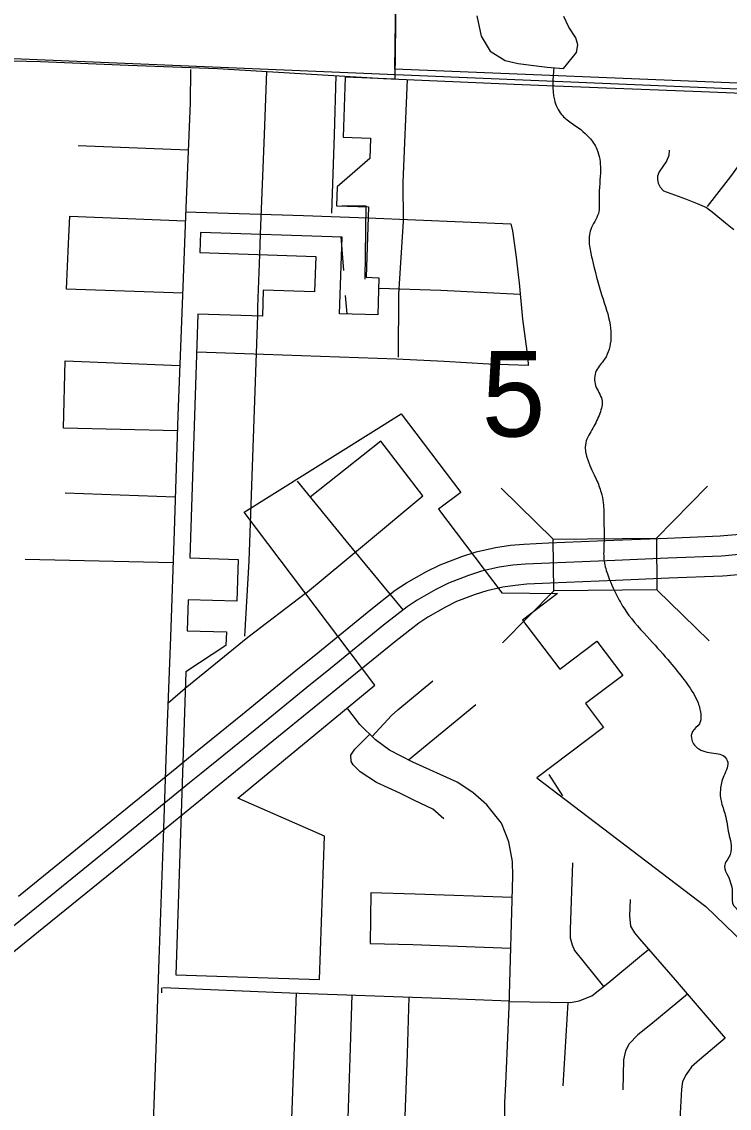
# Model space of a CAD drawing. Extents: x 1219626 to 1426462, y 456797 to 752399.
# Drawn here: x 1346385 to 1349894, y 558376 to 563770 of the extents above; entities that cross this region are included whole.
import ezdxf

# ---------------------------------------------------------------- set-up
doc = ezdxf.new("R2010")
doc.units = 0
for name, color, linetype in [('Bridges', 7, 'Continuous'), ('Cities Incorporated Area', 7, 'Continuous'), ('City Streets', 7, 'Continuous'), ('Connecting Roads', 7, 'Continuous'), ('County Routes Highway Center Lines', 7, 'Continuous'), ('Lakes and Ponds', 7, 'Continuous'), ('Local Roads Paved', 7, 'Continuous'), ('Masks', 7, 'Continuous'), ('Narrow River Creek and Branch and Slough', 7, 'Continuous'), ('Section Lines', 7, 'Continuous'), ('Section Numbers', 7, 'Continuous'), ('State Route Divided Highway Outline and Fill', 7, 'Continuous'), ('State Routes Highway Center Lines', 7, 'Continuous')]:
    doc.layers.add(name, color=color, linetype=linetype)

msp = doc.modelspace()

# ---------------------------------------------------------------- linework, layer by layer
at = {"layer": 'Bridges'}
for p, q in [((1349021, 561201.4), (1348762.5, 561454.9)), ((1349533, 561206.4), (1349786.5, 561464.9)), ((1349023.5, 560945.4), (1348770, 560687)), ((1349535.5, 560950.4), (1349794, 560696.9))]:
    msp.add_line(p, q, dxfattribs=at)
msp.add_lwpolyline([(1349021, 561201.4), (1349533, 561206.4), (1349535.5, 560950.4), (1349023.5, 560945.4)], close=True, dxfattribs=at)
at = {"layer": 'Cities Incorporated Area'}
for p, q in [((1348335.1, 571362.3), (1348234.8, 563484.7)), ((1347988.5, 563494), (1347978.7, 563196.1)), ((1348234.8, 563484.7), (1347988.5, 563494)), ((1347978.7, 563196.1), (1348114.4, 563191.6)), ((1348114.4, 563191.6), (1348111.1, 563091)), ((1348111.1, 563091), (1347949.3, 562950.4)), ((1347949.3, 562950.4), (1347946.2, 562855.8)), ((1347946.2, 562855.8), (1348104.7, 562850.6)), ((1348104.7, 562850.6), (1348093.2, 562501.2)), ((1347271, 562724.3), (1347267.7, 562623.9)), ((1347973.7, 562701.2), (1347271, 562724.3)), ((1347961.2, 562320.6), (1347973.7, 562701.2)), ((1347267.7, 562623.9), (1347843, 562605)), ((1347843, 562605), (1347837.2, 562428.5)), ((1348093.2, 562501.2), (1348156.7, 562499.1)), ((1348156.7, 562499.1), (1348150.6, 562314.4)), ((1347582.8, 562436.8), (1347578.6, 562308.4)), ((1347837.2, 562428.5), (1347582.8, 562436.8)), ((1347257.7, 562319), (1347217.8, 561108.5)), ((1347578.6, 562308.4), (1347257.7, 562319)), ((1348150.6, 562314.4), (1347961.2, 562320.6)), ((1347487.7, 561334.6), (1348267, 561823.6)), ((1348267, 561823.6), (1348562.1, 561433)), ((1348562.1, 561433), (1348452.4, 561350.2)), ((1348136.2, 560476.3), (1347487.7, 561334.6)), ((1348452.4, 561350.2), (1348765.8, 560935.4)), ((1347217.8, 561108.5), (1347457.8, 561100.6)), ((1347457.8, 561100.6), (1347451, 560893.1)), ((1348765.8, 560935.4), (1349042.6, 560931.8)), ((1347211, 560901), (1347206, 560747.1)), ((1347451, 560893.1), (1347211, 560901)), ((1349042.6, 560931.8), (1348868.2, 560800)), ((1348868.2, 560800), (1349053, 560555.4)), ((1347206, 560747.1), (1347400.1, 560740.7)), ((1347400.1, 560740.7), (1347397.8, 560673.1)), ((1347397.8, 560673.1), (1347199.2, 560542.9)), ((1349053, 560555.4), (1349237.4, 560694.7)), ((1349237.4, 560694.7), (1349365.6, 560525)), ((1347199.2, 560542.9), (1347149.7, 559038.5)), ((1349365.6, 560525), (1349181.2, 560385.7)), ((1347456.6, 559916), (1348136.2, 560476.3)), ((1349181.2, 560385.7), (1349271, 560266.8)), ((1349271, 560266.8), (1348938.9, 560015.9)), ((1347885.7, 559727.7), (1347456.6, 559916)), ((1347862.3, 559015), (1347885.7, 559727.7)), ((1347149.7, 559038.5), (1347862.3, 559015))]:
    msp.add_line(p, q, dxfattribs=at)
msp.add_lwpolyline([(1348938.9, 560015.9), (1349778.8, 559377.2), (1349968.8, 559194.8), (1350791.9, 558387.4)], dxfattribs=at)
at = {"layer": 'City Streets'}
for p, q in [((1346664.8, 563155), (1347210.1, 563134)), ((1347568.2, 562715.3), (1347564.8, 562612.2)), ((1346600.9, 561431), (1347146.3, 561411.6)), ((1346401.5, 561102.8), (1347135.4, 561085.4)), ((1347196, 560460.1), (1347109.7, 560385.5)), ((1348302.9, 560105.5), (1348636.9, 560381)), ((1349071.1, 558487.3), (1349095.6, 558901.7))]:
    msp.add_line(p, q, dxfattribs=at)
for points in [[(1347598.8, 563523.1), (1347587, 563209.6), (1347568.2, 562715.3)], [(1347942.7, 563502.4), (1347934.7, 563208.7), (1347921.9, 562819.3)], [(1347196.9, 562826.7), (1347782.1, 562807.3), (1348100.9, 562796.2)], [(1347183, 562422.4), (1346606, 562442.6), (1346617.1, 562666.7), (1346623.1, 562804.8), (1347195.3, 562781.3)], [(1347564.8, 562612.2), (1347554.6, 562354.8), (1347553.7, 562311.3)], [(1347157.4, 561738.9), (1346592.4, 561753.1), (1346600.9, 562086.3), (1347169.4, 562063.2)], [(1347791.9, 560932.4), (1348084.2, 561175.3), (1348374.9, 561416.5), (1348166.1, 561688.3), (1347815.1, 561410.4)], [(1347751, 561488.9), (1347993.1, 561192.3), (1348275.5, 560850)], [(1348122.5, 560221.9), (1348219.3, 560326.4), (1348250, 560354.6), (1348423.9, 560497.8)], [(1348750.7, 556857.9), (1348759.6, 557059), (1348770.7, 557242.2), (1348775.8, 557428), (1348795.4, 557951.3), (1348798, 558065.5), (1348792, 558147.3), (1348788.6, 558198.4), (1348781, 558286.2), (1348781, 558404.6), (1348786.1, 558497.5), (1348803.1, 558880.2), (1348820.2, 559528.8), (1348818.5, 559602), (1348800.6, 559699.2), (1348763.9, 559792.1), (1348691.5, 559883.3), (1348622.4, 559943.8), (1348544.9, 559994.9), (1348324.2, 560094.6), (1348209.1, 560153.4), (1348140.1, 560204.6), (1348061.7, 560282.1), (1348002.9, 560358.8)], [(1348478.3, 559812.5), (1348423.9, 559861.1), (1348330.1, 559905.4), (1348259.4, 559940.4), (1348144.3, 559994.1), (1348064.2, 560046.9), (1348029.3, 560081.9), (1348018.2, 560098), (1348017.3, 560129.6), (1348036.9, 560159.4), (1348111.5, 560232.9)], [(1349115.9, 559595.2), (1349105.7, 559263.7), (1349105.7, 559222.8), (1349114.2, 559187.9), (1349127, 559158.9), (1349269.9, 558980.5)], [(1348817.4, 559422.2), (1348336.1, 559439.3), (1348117.1, 559445.2), (1348113.6, 559193.8), (1348325, 559188.7), (1348810.8, 559171.1)], [(1349402.2, 559412.8), (1349398.8, 559331), (1349404.8, 559279.9), (1349424.4, 559247.5), (1349448.3, 559216.8), (1349626.4, 559013.1), (1349873.5, 558724.2), (1349746.5, 558616.9), (1349706.5, 558581.9), (1349680.1, 558544.4), (1349663, 558508.6), (1349657.9, 558471.1), (1349641.5, 558173.6)], [(1348803.8, 558906.9), (1349107.4, 558901.5), (1349150, 558909.2), (1349213, 558934.7), (1349291.4, 558997.8), (1349459.3, 559136.7), (1349493.7, 559164.8)], [(1347085.4, 558975.6), (1347715.2, 558950.1), (1348464.3, 558922.8), (1348803.9, 558910)], [(1347745.4, 558949), (1347734.8, 558636.5), (1347719.5, 558235)], [(1347999.9, 558228.2), (1348014.4, 558624.5), (1348024.3, 558938.8)], [(1349686.3, 558943), (1349505.4, 558792.8), (1349441, 558740.4), (1349398.4, 558697), (1349379.7, 558661.2), (1349370.3, 558616), (1349366, 558467.7)], [(1348304.5, 558928.6), (1348296.5, 558645.8), (1348280.3, 558204.4), (1348474.6, 558200.1)]]:
    msp.add_lwpolyline(points, dxfattribs=at)
at = {"layer": 'Connecting Roads'}
msp.add_lwpolyline([(1347222.4, 563532.6), (1347219.4, 563368.1), (1347198.1, 562845.7), (1347179.4, 562324.1), (1347158.9, 561815.3), (1347141, 561240.9), (1347122.3, 560715.1), (1347103.5, 560205.4), (1347085.6, 559717.1), (1347065.2, 559114.6), (1347048.1, 558622.8), (1347029.4, 558124.3)], dxfattribs=at)
at = {"layer": 'County Routes Highway Center Lines'}
msp.add_lwpolyline([(1341197, 563735.1), (1341867.5, 563703.6), (1342500.1, 563681.3), (1343520.8, 563640.5), (1344311.5, 563612.4), (1345034.4, 563604.6), (1345994.9, 563583.3), (1346478.1, 563572.6), (1346912.8, 563555.1), (1347356.2, 563537.7), (1348178.9, 563488.2), (1348828, 563460.1), (1349028.9, 563452.3), (1349756.5, 563423.2), (1350691.9, 563386.3), (1351274, 563363), (1351525.3, 563348.5), (1351971.6, 563324.2)], dxfattribs=at)
msp.add_arc((1345880.6, 559007), 1200, 357.2434, 358.4008, dxfattribs=at)
at = {"layer": 'Lakes and Ponds'}
for points in [[(1348642.1, 563798.7), (1348663.4, 563699), (1348708.2, 563624.2), (1348782.4, 563578.1), (1348846.5, 563563), (1348911.2, 563554.3), (1348991.5, 563545.2), (1349071.8, 563538.4)], [(1349071.8, 563538.4), (1349135.9, 563616.6), (1349143.2, 563655.4), (1349132.7, 563690.5), (1349097.8, 563742.7), (1349073.8, 563796.1)]]:
    msp.add_lwpolyline(points, dxfattribs=at)
at = {"layer": 'Local Roads Paved'}
for points in [[(1348253.5, 562104.4), (1348256, 562417.4), (1348279, 562779.8), (1348277.3, 562972.9), (1348297.6, 563483)], [(1349934.3, 563159.2), (1349943.7, 563119.2), (1349942.8, 563078.4), (1349935.2, 563050.3), (1349900.3, 563000.9), (1349784.6, 562852.1)], [(1349596.8, 563132.8), (1349594.1, 563106.4), (1349582.2, 563078.4), (1349565.2, 563051.1), (1349546.5, 563024.8), (1349538.8, 563002.6), (1349537.9, 562986.5), (1349541.3, 562967.8), (1349550.7, 562948.2), (1349568.6, 562931.2), (1349676.6, 562891.2), (1349734.4, 562867.4), (1349781.2, 562847), (1349817, 562819.8), (1349875.6, 562771.3), (1349917.3, 562738.1)], [(1348100.9, 562796.2), (1348811.5, 562767), (1348819.2, 562731.3), (1348837, 562602), (1348847.2, 562513.5), (1348851.5, 562473.5), (1348869.3, 562293.2), (1348894.9, 562098.4), (1348896.6, 562063.5), (1348700.9, 562069.5), (1348480.6, 562084), (1348243.3, 562094.2), (1347583.2, 562118.8), (1347254.8, 562129)], [(1348157.4, 562447.2), (1348463.6, 562437), (1348857, 562418.2)], [(1347553.7, 562311.3), (1347511.1, 561091.8), (1347489, 560720.2)], [(1347791.9, 560932.4), (1347506.9, 560712.5), (1347196, 560460.1)]]:
    msp.add_lwpolyline(points, dxfattribs=at)
at = {"layer": 'Masks'}
for p, q in [((1348093.2, 562854.4), (1347971.8, 562854.8)), ((1348088.6, 562491.8), (1348093.2, 562854.4))]:
    msp.add_line(p, q, dxfattribs=at)
for points in [[(1347967, 562701.4), (1347980, 562535.4)], [(1347989.7, 562410.8), (1347996.8, 562319.9)], [(1349067.9, 559928.1), (1349001.2, 560033.8)]]:
    msp.add_lwpolyline(points, dxfattribs=at)
at = {"layer": 'Narrow River Creek and Branch and Slough'}
msp.add_spline([(1349023.9, 563542.5), (1349027, 563382.5), (1349061.6, 563309.8), (1349110, 563268.3), (1349199.9, 563195.6), (1349237.9, 563136.8), (1349255.2, 563036.5), (1349248.3, 562894.6), (1349244.8, 562818.5), (1349206.8, 562738.9), (1349199.9, 562666.2), (1349213.7, 562593.6), (1349262.1, 562410.2), (1349303.6, 562264.8), (1349307.1, 562199.1), (1349276, 562095.3), (1349234.5, 562036.5), (1349231, 561963.8), (1349262.1, 561894.6), (1349251.8, 561825.4), (1349217.2, 561752.7), (1349182.6, 561680), (1349234.5, 561499.2), (1349258.7, 561433.4), (1349269, 561381.5), (1349272.5, 561298.5), (1349272.5, 561177.4), (1349272.5, 561101.3), (1349289.8, 561028.6), (1349338.2, 560917.9), (1349383.2, 560841.7), (1349500.8, 560703.3), (1349601, 560589.1), (1349670.2, 560502.6), (1349739.4, 560388.4), (1349753.2, 560326.2), (1349746.3, 560284.6), (1349711.7, 560246.6), (1349708.3, 560205.1), (1349742.8, 560160.1), (1349829.3, 560137.5), (1349863.9, 560127.1), (1349884.6, 560102.9), (1349867.3, 560026.8), (1349850, 559957.6), (1349853.5, 559902.2), (1349874.3, 559833), (1349891.5, 559739.6), (1349901.9, 559694.6), (1349898.5, 559635.8), (1349870.8, 559577), (1349888.1, 559528.5), (1349908.8, 559438.5), (1349915.8, 559383.2), (1349933, 559362.4), (1349936.5, 559345.1), (1350012.6, 559307.1), (1350144, 559265.5), (1350189, 559241.3), (1350233.9, 559192.9), (1350278.9, 559106.4), (1350352.5, 558991.7), (1350421.7, 558894.8), (1350632.7, 558659.5), (1350722.6, 558566.1), (1350767.5, 558493.4), (1350802.1, 558451.9), (1350864.4, 558400), (1350957.7, 558351.6), (1350982, 558310.1), (1350971.6, 558261.6), (1350940.5, 558213.2), (1350964.7, 558171.6), (1351013.1, 558130.1), (1351116.8, 558043.6), (1351196.4, 558002.1), (1351244.8, 558022.9), (1351317.4, 558047.1), (1351417.7, 558050.5), (1351493.8, 558022.9), (1351611.4, 557943.3), (1351773.9, 557780.6), (1351877.7, 557673.4), (1351898.4, 557611.1), (1351919.2, 557562.6), (1351939.9, 557528), (1351978, 557476.1), (1351988.3, 557410.4), (1351995.2, 557320.4), (1352022.9, 557265.1), (1352078.2, 557213.2)], degree=3, dxfattribs=at)
at = {"layer": 'Section Lines'}
msp.add_line((1346144.5, 563595.9), (1351486, 563371.1), dxfattribs=at)
at = {"layer": 'State Route Divided Highway Outline and Fill'}
for points in [[(1346368.5, 559428.5), (1346749.2, 559737.9), (1347154.2, 560068.7), (1347212, 560115.8), (1347479.8, 560333.1), (1347735.8, 560542.1), (1347852.8, 560637.7), (1348116.5, 560852.3), (1348237.8, 560947.5), (1348294, 560984.6), (1348392.4, 561040.5), (1348461, 561074.8), (1348567.3, 561116), (1348638.8, 561138.6), (1348734.2, 561160.3), (1348809.5, 561170.9), (1348875.9, 561177.2), (1348997.8, 561182.6), (1349321.6, 561196.2), (1349586.1, 561206.9), (1349849.5, 561217.5), (1349868, 561218.8), (1349946.5, 561225.8)], [(1349969.2, 561027), (1349883.8, 561019.4), (1349860.5, 561017.8), (1349594.2, 561007), (1349329.9, 560996.4), (1349006.5, 560982.8), (1348889.8, 560977.6), (1348832.9, 560972.2), (1348770.4, 560963.4), (1348691.2, 560945.4), (1348633.6, 560927.2), (1348542, 560891.7), (1348486.5, 560863.9), (1348398.6, 560814), (1348354.8, 560785.2), (1348241.4, 560696.1), (1347979.2, 560482.7), (1347862.3, 560387.2), (1347606.1, 560178), (1347338.2, 559960.7), (1347280.6, 559913.7), (1346875.5, 559582.8), (1346494.5, 559273.2), (1346326.8, 559137.4)]]:
    msp.add_lwpolyline(points, dxfattribs=at)
at = {"layer": 'State Routes Highway Center Lines'}
for p, q in [((1348235.9, 563534.5), (1348269, 566133.7)), ((1351529.5, 563398.5), (1348235.9, 563534.5))]:
    msp.add_line(p, q, dxfattribs=at)
msp.add_lwpolyline([(1349957.9, 561126.4), (1349875.9, 561119.1), (1349855, 561117.6), (1349590.1, 561107), (1349325.8, 561096.3), (1349002.2, 561082.7), (1348882.8, 561077.4), (1348821.2, 561071.6), (1348752.3, 561061.8), (1348665, 561042), (1348600.5, 561021.6), (1348501.5, 560983.3), (1348439.4, 560952.2), (1348346.3, 560899.3), (1348296.3, 560866.3), (1348178.9, 560774.2), (1347916, 560560.2), (1347799.1, 560464.7), (1347542.9, 560255.6), (1347275.1, 560038.2), (1347217.4, 559991.2), (1346812.3, 559660.3), (1346431.5, 559350.8), (1346263.7, 559215)], dxfattribs=at)

# ---------------------------------------------------------------- texts
at = {"layer": 'Section Numbers'}
msp.add_text('5', height=425, rotation=359.9997, dxfattribs=at).set_placement((1348666.1, 561710.8))

doc.saveas('drawing.dxf')
